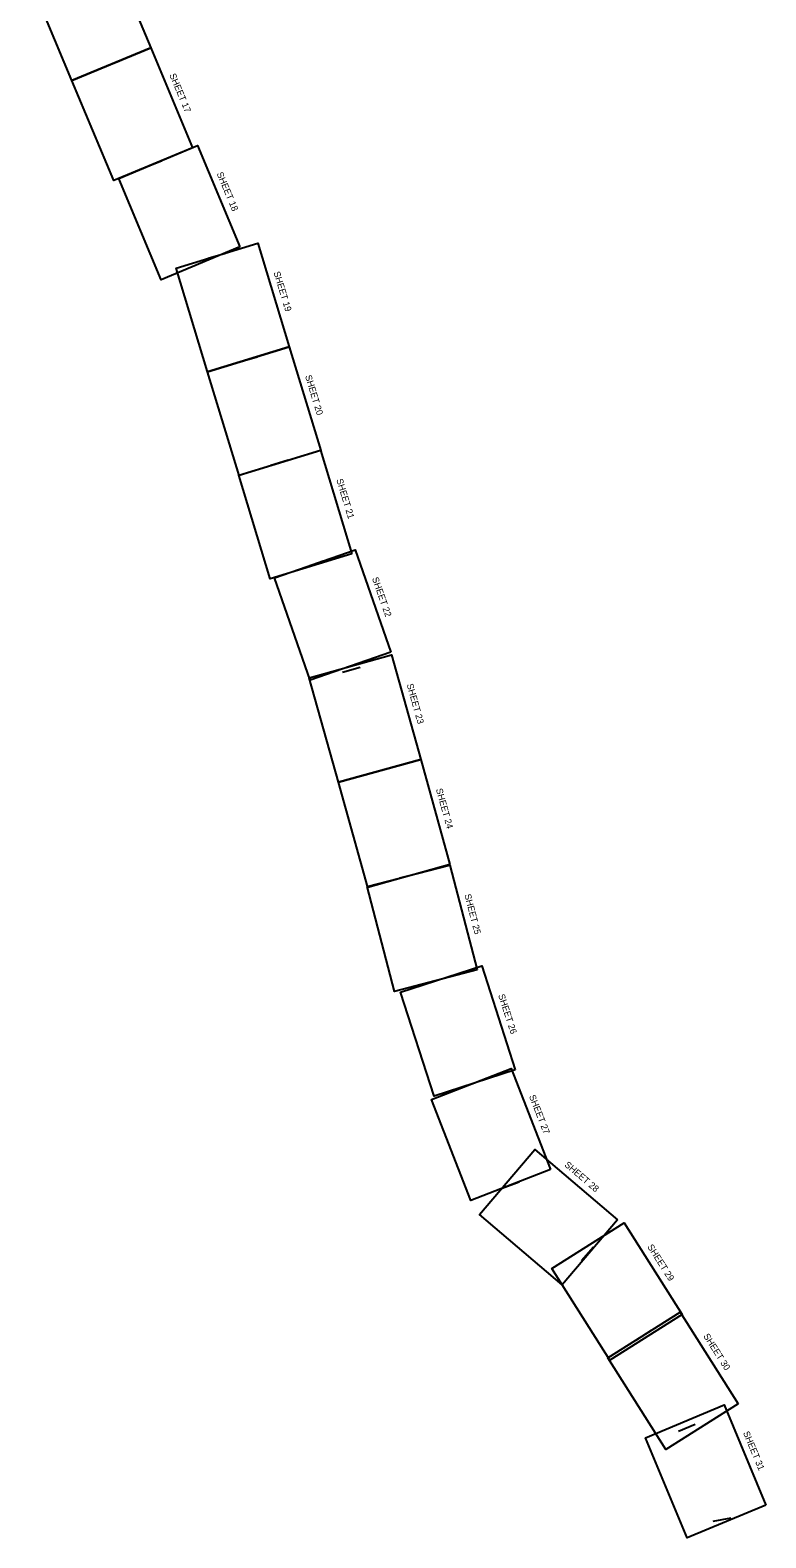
# Model space of a CAD drawing. Extents: x 585633 to 623435, y 1850221 to 1940301.
# Drawn here: x 601033 to 623435, y 1850221 to 1896122 of the extents above; entities that cross this region are included whole.
import ezdxf

# ---------------------------------------------------------------- set-up
doc = ezdxf.new("R2010")
doc.units = 0
for name, color, linetype in [('C-CHAN-LIMT-HIST', 7, 'Continuous'), ('V-ANNO-DIMS', 7, 'Continuous'), ('V-CHAN-CNTR-IDEN', 7, 'Continuous')]:
    doc.layers.add(name, color=color, linetype=linetype)

msp = doc.modelspace()

# ---------------------------------------------------------------- linework, layer by layer
at = {"layer": 'V-ANNO-DIMS'}
for p, q in [((603252, 1894980), (603759, 1895193)), ((604525, 1891936), (605033, 1892148)), ((606456, 1889177), (606982, 1889337)), ((607416, 1886020), (607942, 1886180)), ((608364, 1882876), (608890, 1883036)), ((609440, 1879781), (609959, 1879962)), ((610549, 1876580), (611078, 1876728)), ((611408, 1873498), (611938, 1873646)), ((612290, 1870310), (612822, 1870448)), ((613286, 1867148), (613810, 1867317)), ((614208, 1863939), (614721, 1864138)), ((615407, 1860864), (615920, 1861064)), ((617825, 1858665), (618182, 1859084)), ((619492, 1856251), (619957, 1856545)), ((620779, 1853468), (621286, 1853679)), ((621834, 1850728), (622375, 1850826))]:
    msp.add_line(p, q, dxfattribs=at)
at = {"layer": 'V-CHAN-CNTR-IDEN'}
for points in [[(604705, 1895588), (602306, 1894585), (601033, 1897630), (603432, 1898633)], [(605978, 1892543), (603579, 1891540), (602306, 1894585), (604705, 1895588)], [(607423, 1889527), (605024, 1888524), (603735, 1891606), (606134, 1892609)], [(608923, 1886478), (606435, 1885721), (605475, 1888879), (607963, 1889635)], [(609883, 1883321), (607395, 1882564), (606435, 1885721), (608923, 1886478)], [(610831, 1880177), (608343, 1879421), (607383, 1882578), (609871, 1883335)], [(612013, 1877183), (609557, 1876328), (608472, 1879444), (610927, 1880299)], [(612925, 1873921), (610421, 1873223), (609534, 1876401), (612039, 1877100)], [(613817, 1870723), (611313, 1870025), (610421, 1873223), (612925, 1873921)], [(614641, 1867510), (612124, 1866858), (611297, 1870053), (613814, 1870704)], [(615805, 1864472), (613331, 1863672), (612311, 1866832), (614785, 1867632)], [(616875, 1861436), (614452, 1860492), (613254, 1863566), (615676, 1864511)], [(618915, 1859900), (617229, 1857921), (614717, 1860061), (616403, 1862040)], [(620884, 1857026), (618687, 1855634), (616921, 1858421), (619117, 1859813)], [(622589, 1854306), (620393, 1852915), (618626, 1855702), (620822, 1857094)], [(623435, 1851221), (621034, 1850221), (619766, 1853268), (622166, 1854267)]]:
    msp.add_lwpolyline(points, close=True, dxfattribs=at)

# ---------------------------------------------------------------- texts
at = {"layer": 'C-CHAN-LIMT-HIST'}
for s, rotation, p in [('SHEET 17', 292.6922, (605269, 1894757)), ('SHEET 18', 292.6922, (606708, 1891755)), ('SHEET 19', 286.9139, (608442, 1888745)), ('SHEET 20', 286.9139, (609402, 1885590)), ('SHEET 21', 286.9139, (610353, 1882435)), ('SHEET 22', 289.2061, (611441, 1879431)), ('SHEET 23', 285.583, (612497, 1876200)), ('SHEET 24', 285.583, (613387, 1873010)), ('SHEET 25', 284.509, (614255, 1869798)), ('SHEET 26', 287.8935, (615282, 1866743)), ('SHEET 27', 291.3024, (616220, 1863666)), ('SHEET 28', 319.5713, (617286, 1861551)), ('SHEET 29', 302.3679, (619816, 1859083)), ('SHEET 30', 302.3679, (621521, 1856366)), ('SHEET 31', 292.6009, (622736, 1853420))]:
    msp.add_text(s, height=200, rotation=rotation, dxfattribs=at).set_placement(p)

doc.saveas('drawing.dxf')
